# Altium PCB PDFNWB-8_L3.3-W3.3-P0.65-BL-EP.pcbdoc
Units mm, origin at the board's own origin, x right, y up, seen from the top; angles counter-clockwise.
Board outline 16.06 x 16.74 mm, 2 copper layers (Top Layer, Bottom Layer), stack 0 mm thick; 1 components, 0 nets, 11 pads, 0 vias.
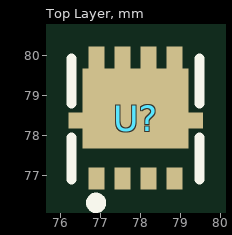
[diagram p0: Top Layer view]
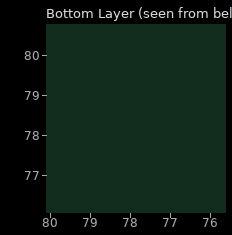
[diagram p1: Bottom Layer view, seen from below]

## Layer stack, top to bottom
Top Layer: signal copper (thickness not stored)
Bottom Layer: signal copper (thickness not stored)

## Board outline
85.91,69.85 69.85,69.85 69.85,86.587 85.91,86.587

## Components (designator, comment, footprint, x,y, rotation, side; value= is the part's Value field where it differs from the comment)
U? "" PDFNWB-8_L3.3-W3.3-P0.65-BL-EP 77.88,78.437 r0 top

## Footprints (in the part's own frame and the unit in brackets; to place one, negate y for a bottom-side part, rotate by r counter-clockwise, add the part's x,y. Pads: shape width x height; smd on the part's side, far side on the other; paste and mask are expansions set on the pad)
PDFNWB-8_L3.3-W3.3-P0.65-BL-EP [mm]
  rect 0.4x0.56 smd paste-100 mask+0.05: 1(-0.975,-1.5) 2(-0.325,-1.5) 3(0.325,-1.5) 4(0.975,-1.5)
  rect 0.4x0.6 smd paste-100 mask+0.05: 5(0.975,1.5) 6(0.325,1.5) 7(-0.325,1.5) 8(-0.975,1.5)
  rect 0.56x0.4 smd paste-100 mask+0.05: 9(-1.4,-0.05) 9(1.4,-0.05)
  rect 2.65x2 smd paste-100 mask+0.05: 9(0,0.25)
  silkscreen extent -1.6,-2.24 1.6,1.5

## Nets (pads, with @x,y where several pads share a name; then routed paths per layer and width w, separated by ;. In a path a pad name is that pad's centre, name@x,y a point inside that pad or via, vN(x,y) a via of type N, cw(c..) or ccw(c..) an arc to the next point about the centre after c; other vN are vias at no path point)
pads on no net: U?.1 U?.2 U?.3 U?.4 U?.5 U?.6 U?.7 U?.8 U?.9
